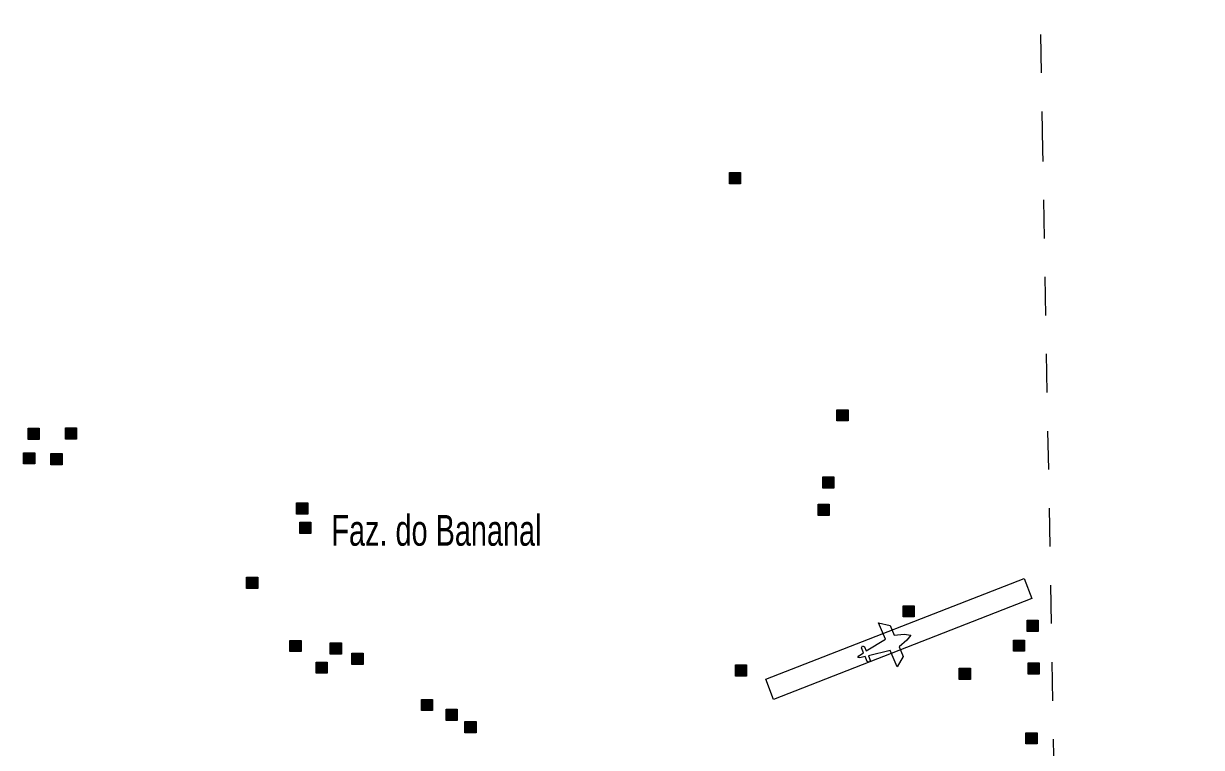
# Model space of a CAD drawing. Extents: x 220.8 to 246.7, y 7287.6 to 7315.8.
# Drawn here: x 243.593 to 246.651, y 7309.345 to 7311.223 of the extents above; entities that cross this region are included whole.
import ezdxf

# ---------------------------------------------------------------- set-up
doc = ezdxf.new("R2010")
doc.units = 0
doc.header["$LTSCALE"] = 0.032
doc.linetypes.add('SHORT_DASHED', pattern=[2.7, 1.5, -1.2])
for name, color, linetype, lineweight in [('17', 7, 'Continuous', 25), ('18', 7, 'Continuous', 13), ('2', 7, 'Continuous', 25), ('58', 7, 'SHORT_DASHED', 13)]:
    doc.layers.add(name, color=color, linetype=linetype, lineweight=lineweight)
doc.layers.add('61', color=7, linetype='Continuous')

msp = doc.modelspace()

# ---------------------------------------------------------------- hatches: boundary and pattern name
at = {"layer": '2'}
for points in [[(245.4253, 7310.8366), (245.4543, 7310.8366), (245.4543, 7310.8076), (245.4253, 7310.8076)], [(245.7045, 7310.2209), (245.7335, 7310.2209), (245.7335, 7310.1919), (245.7045, 7310.1919)], [(243.6049, 7310.1731), (243.6339, 7310.1731), (243.6339, 7310.1441), (243.6049, 7310.1441)], [(243.7017, 7310.1741), (243.7307, 7310.1741), (243.7307, 7310.1451), (243.7017, 7310.1451)], [(243.5931, 7310.1096), (243.6221, 7310.1096), (243.6221, 7310.0806), (243.5931, 7310.0806)], [(243.6641, 7310.1074), (243.6931, 7310.1074), (243.6931, 7310.0784), (243.6641, 7310.0784)], [(245.6678, 7310.0469), (245.6968, 7310.0469), (245.6968, 7310.0179), (245.6678, 7310.0179)], [(244.3019, 7309.9791), (244.3309, 7309.9791), (244.3309, 7309.9501), (244.3019, 7309.9501)], [(245.6555, 7309.9758), (245.6845, 7309.9758), (245.6845, 7309.9468), (245.6555, 7309.9468)], [(244.3102, 7309.9293), (244.3392, 7309.9293), (244.3392, 7309.9003), (244.3102, 7309.9003)], [(244.1719, 7309.7865), (244.2009, 7309.7865), (244.2009, 7309.7575), (244.1719, 7309.7575)], [(245.8763, 7309.7126), (245.9053, 7309.7126), (245.9053, 7309.6836), (245.8763, 7309.6836)], [(246.1979, 7309.6747), (246.2269, 7309.6747), (246.2269, 7309.6457), (246.1979, 7309.6457)], [(244.2846, 7309.6225), (244.3136, 7309.6225), (244.3136, 7309.5935), (244.2846, 7309.5935)], [(246.1627, 7309.6234), (246.1917, 7309.6234), (246.1917, 7309.5944), (246.1627, 7309.5944)], [(244.3891, 7309.6158), (244.4181, 7309.6158), (244.4181, 7309.5868), (244.3891, 7309.5868)], [(244.3526, 7309.5661), (244.3816, 7309.5661), (244.3816, 7309.5371), (244.3526, 7309.5371)], [(244.4454, 7309.5893), (244.4744, 7309.5893), (244.4744, 7309.5603), (244.4454, 7309.5603)], [(246.2006, 7309.5639), (246.2296, 7309.5639), (246.2296, 7309.5349), (246.2006, 7309.5349)], [(245.4408, 7309.5587), (245.4698, 7309.5587), (245.4698, 7309.5297), (245.4408, 7309.5297)], [(246.0222, 7309.5504), (246.0512, 7309.5504), (246.0512, 7309.5214), (246.0222, 7309.5214)], [(244.626, 7309.4693), (244.655, 7309.4693), (244.655, 7309.4403), (244.626, 7309.4403)], [(244.6898, 7309.4438), (244.7188, 7309.4438), (244.7188, 7309.4148), (244.6898, 7309.4148)], [(244.7387, 7309.4119), (244.7677, 7309.4119), (244.7677, 7309.3829), (244.7387, 7309.3829)], [(246.1952, 7309.3829), (246.2242, 7309.3829), (246.2242, 7309.3539), (246.1952, 7309.3539)]]:
    msp.add_hatch(color=256, dxfattribs=at).paths.add_polyline_path(points)

# ---------------------------------------------------------------- linework, layer by layer
at = {"layer": '17'}
msp.add_lwpolyline([(245.8959, 7309.6364), (245.8856, 7309.623), (245.8659, 7309.6061), (245.8765, 7309.581), (245.8608, 7309.5541), (245.8429, 7309.5963), (245.7862, 7309.5821), (245.7909, 7309.5711), (245.7887, 7309.5657), (245.7833, 7309.5679), (245.7779, 7309.5803), (245.7639, 7309.5771), (245.7588, 7309.5783), (245.7614, 7309.5828), (245.7737, 7309.5904), (245.7683, 7309.6028), (245.7705, 7309.6083), (245.776, 7309.606), (245.7805, 7309.5955), (245.8302, 7309.626), (245.8123, 7309.6683), (245.8426, 7309.661), (245.8532, 7309.6358), (245.8791, 7309.6384)], close=True, dxfattribs=at)
at = {"layer": '18'}
msp.add_lwpolyline([(245.5197, 7309.5215), (246.1903, 7309.7827), (246.2105, 7309.731), (245.5402, 7309.4691)], close=True, dxfattribs=at)
at = {"layer": '2'}
for points in [[(245.4253, 7310.8366), (245.4543, 7310.8366), (245.4543, 7310.8076), (245.4253, 7310.8076)], [(245.7045, 7310.2209), (245.7335, 7310.2209), (245.7335, 7310.1919), (245.7045, 7310.1919)], [(243.6049, 7310.1731), (243.6339, 7310.1731), (243.6339, 7310.1441), (243.6049, 7310.1441)], [(243.7017, 7310.1741), (243.7307, 7310.1741), (243.7307, 7310.1451), (243.7017, 7310.1451)], [(243.5931, 7310.1096), (243.6221, 7310.1096), (243.6221, 7310.0806), (243.5931, 7310.0806)], [(243.6641, 7310.1074), (243.6931, 7310.1074), (243.6931, 7310.0784), (243.6641, 7310.0784)], [(245.6678, 7310.0469), (245.6968, 7310.0469), (245.6968, 7310.0179), (245.6678, 7310.0179)], [(244.3019, 7309.9791), (244.3309, 7309.9791), (244.3309, 7309.9501), (244.3019, 7309.9501)], [(245.6555, 7309.9758), (245.6845, 7309.9758), (245.6845, 7309.9468), (245.6555, 7309.9468)], [(244.3102, 7309.9293), (244.3392, 7309.9293), (244.3392, 7309.9003), (244.3102, 7309.9003)], [(244.1719, 7309.7865), (244.2009, 7309.7865), (244.2009, 7309.7575), (244.1719, 7309.7575)], [(245.8763, 7309.7126), (245.9053, 7309.7126), (245.9053, 7309.6836), (245.8763, 7309.6836)], [(246.1979, 7309.6747), (246.2269, 7309.6747), (246.2269, 7309.6457), (246.1979, 7309.6457)], [(244.2846, 7309.6225), (244.3136, 7309.6225), (244.3136, 7309.5935), (244.2846, 7309.5935)], [(246.1627, 7309.6234), (246.1917, 7309.6234), (246.1917, 7309.5944), (246.1627, 7309.5944)], [(244.3891, 7309.6158), (244.4181, 7309.6158), (244.4181, 7309.5868), (244.3891, 7309.5868)], [(244.3526, 7309.5661), (244.3816, 7309.5661), (244.3816, 7309.5371), (244.3526, 7309.5371)], [(244.4454, 7309.5893), (244.4744, 7309.5893), (244.4744, 7309.5603), (244.4454, 7309.5603)], [(246.2006, 7309.5639), (246.2296, 7309.5639), (246.2296, 7309.5349), (246.2006, 7309.5349)], [(245.4408, 7309.5587), (245.4698, 7309.5587), (245.4698, 7309.5297), (245.4408, 7309.5297)], [(246.0222, 7309.5504), (246.0512, 7309.5504), (246.0512, 7309.5214), (246.0222, 7309.5214)], [(244.626, 7309.4693), (244.655, 7309.4693), (244.655, 7309.4403), (244.626, 7309.4403)], [(244.6898, 7309.4438), (244.7188, 7309.4438), (244.7188, 7309.4148), (244.6898, 7309.4148)], [(244.7387, 7309.4119), (244.7677, 7309.4119), (244.7677, 7309.3829), (244.7387, 7309.3829)], [(246.1952, 7309.3829), (246.2242, 7309.3829), (246.2242, 7309.3539), (246.1952, 7309.3539)]]:
    msp.add_lwpolyline(points, close=True, dxfattribs=at)
at = {"layer": '58'}
msp.add_lwpolyline([(246.6507, 7288.0853), (246.6212, 7289.7146), (246.5917, 7291.3439), (246.5622, 7292.9732), (246.5328, 7294.6024), (246.5034, 7296.2317), (246.4739, 7297.861), (246.4446, 7299.4903), (246.4152, 7301.1196), (246.3858, 7302.7489), (246.3565, 7304.3782), (246.3272, 7306.0075), (246.2979, 7307.6367), (246.2685, 7309.266), (246.2393, 7310.8953), (246.21, 7312.5246), (246.1808, 7314.1539), (246.1516, 7315.7832)], dxfattribs=at)

# ---------------------------------------------------------------- texts
at = {"layer": '61', "width": 0.7}
msp.add_text('Faz. do Bananal', height=0.08, dxfattribs=at).set_placement((244.3922, 7309.8682))

doc.saveas('drawing.dxf')
